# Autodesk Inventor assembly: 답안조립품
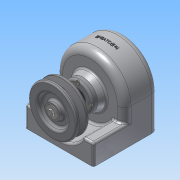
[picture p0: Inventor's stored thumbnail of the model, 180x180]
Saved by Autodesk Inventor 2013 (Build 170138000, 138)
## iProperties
Created: 2015-02
Part Number: 답안조립품
Document SubType Name: Assembly
Designer: Administrator
Author: Administrator
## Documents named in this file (14)
- C:\Documents and Settings\Administrator\바탕 화면\450214V1021\답안조립품.iam
- C:\Documents and Settings\Administrator\바탕 화면\450214V1021\1-본체.ipt
- C:\Documents and Settings\Administrator\바탕 화면\450214V1021\베어링 6001.ipt
- C:\Documents and Settings\Administrator\바탕 화면\450214V1021\축.ipt
- C:\Documents and Settings\Administrator\바탕 화면\450214V1021\키5x5.ipt
- C:\Documents and Settings\Administrator\바탕 화면\450214V1021\5-스퍼기어.ipt
- C:\Documents and Settings\Administrator\바탕 화면\450214V1021\축커버.ipt
- C:\Documents and Settings\Administrator\바탕 화면\450214V1021\M3x0.5.ipt
- C:\Documents and Settings\Administrator\바탕 화면\450214V1021\오일실.ipt
- C:\Documents and Settings\Administrator\바탕 화면\450214V1021\키4x4.ipt
- C:\Documents and Settings\Administrator\바탕 화면\450214V1021\4-V-벨트풀리.ipt
- C:\Documents and Settings\Administrator\바탕 화면\450214V1021\와샤.ipt
- C:\Documents and Settings\Administrator\바탕 화면\450214V1021\M5x0.8.ipt
- M5x0.8.ipt
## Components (7 placed, 4 different names)
1. 1-본체:1
2. 4-V-벨트풀리:1 — 각도:4
3. M5x0.8:1 — 각도:5
4. M3x0.5:1
5. M3x0.5:2
6. M3x0.5:3
7. M3x0.5:4
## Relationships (2: Angle 2)
- 각도:4 [Angle]: 4-V-벨트풀리:1
- 각도:5 [Angle]: M5x0.8:1
